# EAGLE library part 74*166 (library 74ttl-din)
8-bit parallel load SHIFT REGISTER
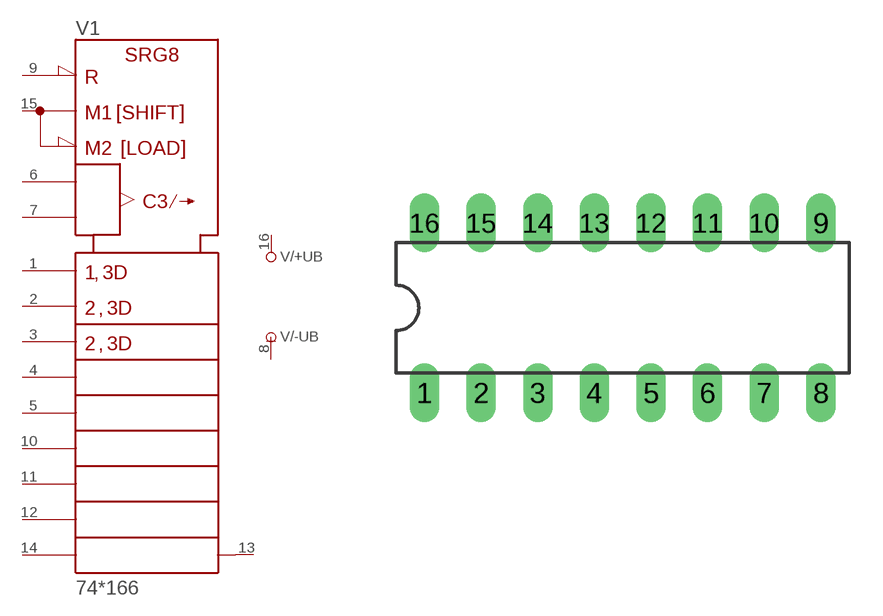
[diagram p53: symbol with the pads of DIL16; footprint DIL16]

Designator prefix V; gates /+UB=+UB /-UB=-UB 1=166

## 74166N  [DIL16]
1  1:SER  in
2  1:A  in
3  1:B  in
4  1:C  in
5  1:D  in
6  1:CLK_INH  in
7  1:CLK  in
8  /-UB:-UB  pwr
9  1:CLR\  in
10  1:E  in
11  1:F  in
12  1:G  in
13  1:QH  out
14  1:H  in
15  1:SH/LD\  in
16  /+UB:+UB  pwr

## Footprint DIL16 (pad centres in mm)
Dual In Line Package
drill 0.813 long: 1 -8.89,-3.81; 2 -6.35,-3.81; 3 -3.81,-3.81; 4 -1.27,-3.81; 5 1.27,-3.81; 6 3.81,-3.81; 7 6.35,-3.81; 8 8.89,-3.81; 9 8.89,3.81; 10 6.35,3.81; 11 3.81,3.81; 12 1.27,3.81; 13 -1.27,3.81; 14 -3.81,3.81; 15 -6.35,3.81; 16 -8.89,3.81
